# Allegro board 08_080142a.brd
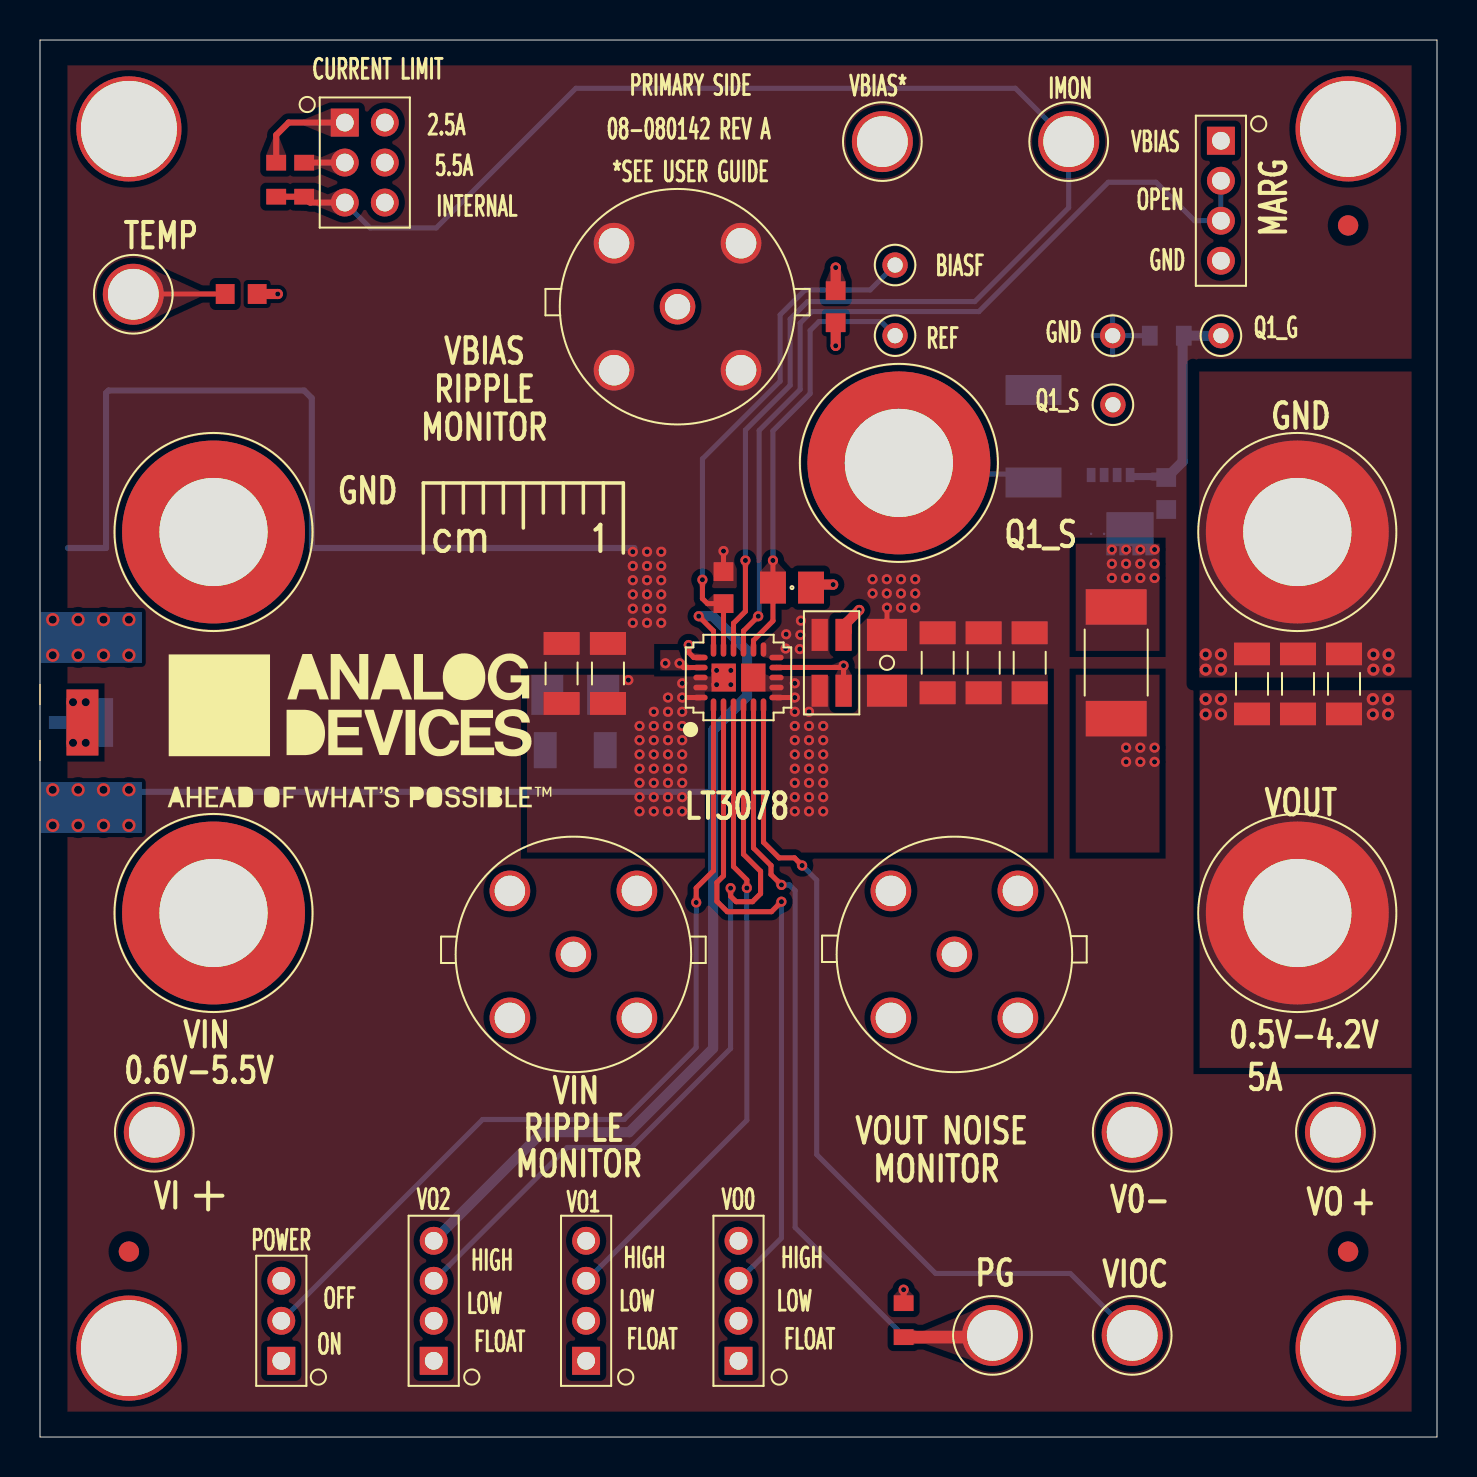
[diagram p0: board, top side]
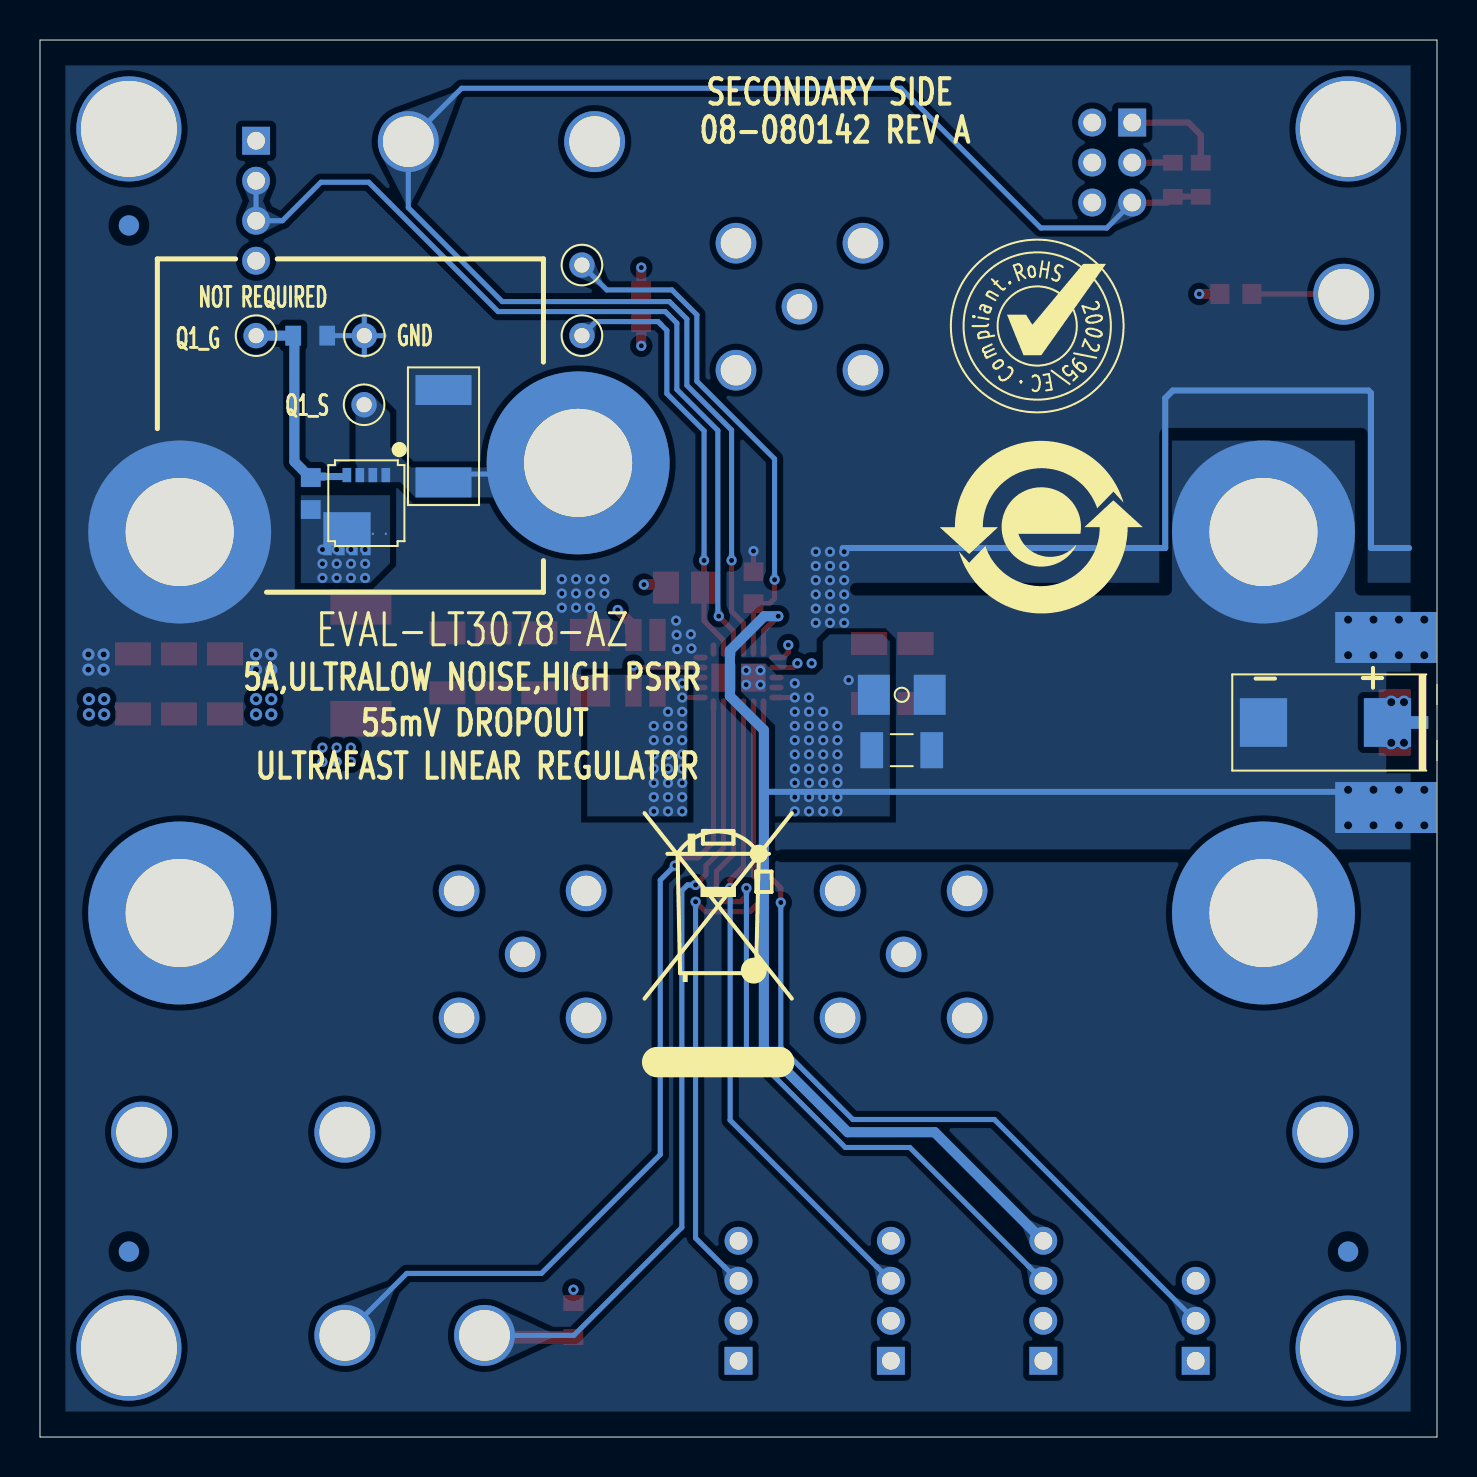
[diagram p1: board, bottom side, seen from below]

Outline 69.85 x 69.85 mm; copper layers: TOP, L2_GND, L3_VCC, BOTTOM. Coordinates in mm from the lower left corner of the outline.
Outline path: 0,69.85 0,0 69.85,0 69.85,69.85 0,69.85

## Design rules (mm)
constraint set DEFAULT: min track width 0.254
net group VBIAS: nets _N38 VBIAS
net group _N16: nets _N14 _N16 _N17
net group VOUT: nets _N86

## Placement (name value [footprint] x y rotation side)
C1  4.7UF  [C0805H60]  37.6 42.47 180 top
C2  2.2uF  [C0603]  34.17 42.47 270 top
C3  10UF  [C1206_SP]  39.58 38.71 270 top
C4  10UF  [C1206H71]  42.35 38.71 270 top
C5  220UF  [C7343-31]  5.58 35.73 0 bottom
C6  TBD0603  [C0603]  39.79 56.52 90 top
C7  TBD1206  [C1206]  44.88 38.71 270 top
C8  TBD1206  [C1206]  47.18 38.71 270 top
C9  TBD1206  [C1206]  49.48 38.71 270 top
C10  TBD1206  [C1206]  60.6 37.66 270 top
C11  TBD1206  [C1206]  62.9 37.66 270 top
C12  TBD1206  [C1206]  65.2 37.66 270 top
C13  TBD0603  [C0603]  10.06 57.15 180 top
C14  TBD1206  [C1206]  28.4 38.18 270 top
C15  TBD1206  [C1206]  26.08 38.18 90 top
C16  4700pF  [C0603]  56.31 47.17 270 bottom
CIN1  47UF  [C1206H71]  26.76 37.11 0 bottom
CIN2  TBD1206  [C1206]  26.76 34.34 180 bottom
E1  2501-2-00-80-00-00-07-0  [CNMILLMAX2501]  42.12 64.77 0 top
E2  2501-2-00-80-00-00-07-0  [CNMILLMAX2501]  4.66 57.14 0 top
E3  2501-2-00-80-00-00-07-0  [CNMILLMAX2501]  5.71 15.24 0 top
E4  2501-2-00-80-00-00-07-0  [CNMILLMAX2501]  47.62 5.08 0 top
E5  2501-2-00-80-00-00-07-0  [CNMILLMAX2501]  54.61 5.08 0 top
E6  2501-2-00-80-00-00-07-0  [CNMILLMAX2501]  54.61 15.24 0 top
E7  2501-2-00-80-00-00-07-0  [CNMILLMAX2501]  64.77 15.24 0 top
E8  2501-2-00-80-00-00-07-0  [CNMILLMAX2501]  51.44 64.77 0 top
J1  575-4  [CNBANANAD312LD203]  8.68 26.2 0 top
J2  575-4  [CNBANANAD312LD203]  8.68 45.25 0 top
J3  112404  [CNAMPHENOL112404]  26.67 24.13 0 top
J4  112404  [CNAMPHENOL112404]  31.88 56.52 0 top
J5  112404  [CNAMPHENOL112404]  45.72 24.13 0 top
J6  575-4  [CNBANANAD312LD203]  62.87 26.2 0 top
J7  575-4  [CNBANANAD312LD203]  62.87 45.25 0 top
J8  142-0701-851  [CNSMAL562W375H166]  0 35.73 180 bottom
J9  575-4  [CNBANANAD312LD203]  42.94 48.7 0 top
JP1  62000311121  [CNTHMHDR1X3L236W79H244]  12.07 3.81 90 top
JP2  62000411121  [CNTHMHDR1X4L315W79H250]  19.69 3.81 90 top
JP3  62000411121  [CNTHMHDR1X4L315W79H250]  27.3 3.81 90 top
JP4  62000411121  [CNTHMHDR1X4L315W79H250]  34.92 3.81 90 top
JP5  62000621121  [CNTHMHDR2X3L236W157H248]  15.24 65.72 270 top
JP6  62000411121  [CNTHMHDR1X4L315W79H250]  59.05 64.81 270 top
NOREF  -  []  0 0 0 top
NOREF#2  -  []  69.85 69.85 180 top
NOREF#3  -  []  154.94 85.09 0 top
NOREF#4  -  []  1.83 65.41 0 top
NOREF#5  -  []  0 69.85 0 top
NOREF#6  -  []  -60.22 175.56 0 top
NOREF#7  -  []  0 0 0 top
NOREF#8  -  [unnamed#2]  65.41 65.41 0 top
NOREF#9  -  []  16 35.31 0 top
NOREF#10  -  []  -111.76 -130.81 0 top
NOREF#11  -  []  0 0 0 top
NOREF#12  -  []  -60.33 196.51 0 top
NOREF#13  -  []  33.92 186.35 0 top
NOREF#14  -  []  306.27 180.04 90 top
NOREF#15  -  []  0 69.85 0 top
NOREF#16  -  []  37.72 62.99 270 top
NOREF#17  -  []  69.85 0 90 top
NOREF#18  -  []  -111.76 -130.81 0 top
NOREF#19  -  [unnamed#2]  4.45 9.27 0 top
NOREF#20  -  []  301.34 180.04 0 top
NOREF#21  -  []  67.77 36.22 0 top
NOREF#22  -  []  67.77 36.22 0 top
NOREF#23  -  []  233.88 183.85 180 top
NOREF#24  -  [unnamed#2]  4.45 65.41 0 top
NOREF#25  -  []  301.27 155.91 0 top
NOREF#26  -  []  0 0 0 top
NOREF#27  -  []  218.47 169.11 0 top
NOREF#28  -  []  218.64 181 0 top
NOREF#29  -  []  0 69.85 270 top
NOREF#30  -  [unnamed#2]  65.41 4.45 0 top
NOREF#31  -  [unnamed#2]  4.45 4.45 0 top
NOREF#32  -  []  66.12 191.41 0 top
NOREF#33  -  []  4.45 4.45 0 top
NOREF#34  -  []  67.77 36.22 0 top
NOREF#35  -  []  35.41 196.51 0 top
NOREF#36  -  []  -73.66 195.58 0 top
NOREF#37  -  []  69.85 0 0 top
NOREF#38  -  []  -111.76 -130.81 0 top
NOREF#39  -  []  0.43 35.73 0 top
NOREF#40  -  []  204.75 192.51 0 top
NOREF#41  -  []  69.85 0 90 top
NOREF#42  -  [unnamed#2]  65.41 60.58 0 top
NOREF#43  -  []  66.93 47.98 0 top
NOREF#44  -  []  178.82 174.9 0 top
NOREF#45  -  []  42.88 66.24 0 top
NOREF#46  -  [unnamed#2]  65.41 9.27 0 top
NOREF#47  -  []  0 0 0 top
NOREF#48  -  []  -60.18 202.21 0 top
NOREF#49  -  []  8.97 196.49 0 top
NOREF#50  -  []  4.45 4.45 0 top
NOREF#51  -  []  0 0 0 top
NOREF#52  -  []  283.59 348.62 0 top
NOREF#53  -  []  -111.76 -130.81 0 top
NOREF#54  -  [unnamed#2]  4.45 9.27 180 bottom
NOREF#55  -  []  19.99 55.55 180 bottom
NOREF#56  -  []  26.67 34.87 180 bottom
NOREF#57  -  [unnamed#2]  65.41 9.27 180 bottom
NOREF#58  -  [unnamed#2]  65.41 60.58 180 bottom
NOREF#59  -  []  19.79 45.49 180 bottom
Q1  FDMC8010  [POWER33]  53.53 46.69 0 bottom
R1  51K  [R0603]  43.18 5.84 90 top
R2  909  [R0603]  13.21 62.87 90 top
R3  2K  [R0603]  11.81 62.87 90 top
R4  TBD_SPACER_2512  [R2512]  53.81 38.71 270 top
R5  0.02  [R2010H35]  49.68 50.04 270 bottom
R6  10K  [R0603]  56.34 55.07 0 bottom
TP1  TESTPAD  [TPC50D30]  42.75 58.6 0 top
TP2  TESTPAD  [TPC50D30]  42.75 55.07 0 top
TP3  TESTPAD  [TPC50D30]  53.65 51.61 90 top
TP4  TESTPAD  [TPC50D30]  53.63 55.07 0 top
TP5  TESTPAD  [TPC50D30]  59.05 55.07 90 top
U1  LT3078AV#PBF  [QFN22_4X3-2PAD]  34.92 37.97 0 top

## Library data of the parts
C1 = CAP: Tolerance: 10; User Part Number: UPN; alternate symbols: (C0805H60); tolerance: 10
C2 C16 = CAP: User Part Number: UPN; Tolerance: 10; alternate symbols: (C0603); tolerance: 10
C3 = CAP_SP: User Part Number: UPN; Tolerance: 10; alternate symbols: (C1206_SP); tolerance: 10
C4 CIN1 = CAP: Tolerance: 10; User Part Number: UPN; alternate symbols: (C1206H71); tolerance: 10
C5 = CAPP: Tolerance: 20; User Part Number: UPN; alternate symbols: (C7343-31); tolerance: 20
C6 C13 = CAP: User Part Number: UPN; alternate symbols: (C0603)
C7-C12 C14 C15 CIN2 = CAP: User Part Number: UPN; alternate symbols: (C1206)
E1-E8 = CNTP1P: User Part Number: UPN; Tolerance: N/A; alternate symbols: (CNMILLMAX2501); tolerance: N/A
J1 J2 J6 J7 J9 = CNTP1P: Tolerance: N/A; User Part Number: UPN; alternate symbols: (CNBANANAD312LD203); tolerance: N/A
J3-J5 = CNBNC5P: Tolerance: N/A; User Part Number: UPN; alternate symbols: (CNAMPHENOL112404); tolerance: N/A
J8 = CNBNC5P: Tolerance: N/A; User Part Number: UPN; alternate symbols: (CNSMAL562W375H166); tolerance: N/A
JP1 = CN3P: User Part Number: UPN; Tolerance: N/A; alternate symbols: (CNTHMHDR1X3L236W79H244); tolerance: N/A
JP2-JP4 JP6 = CN4P: Tolerance: N/A; User Part Number: UPN; alternate symbols: (CNTHMHDR1X4L315W79H250); tolerance: N/A
JP5 = CN6P: User Part Number: UPN; Tolerance: N/A; alternate symbols: (CNTHMHDR2X3L236W157H248); tolerance: N/A
Q1 = TRANNMOSFET_V15: Tolerance: N/A; User Part Number: UPN; alternate symbols: (POWER33); tolerance: N/A
R1 R6 = RES: User Part Number: UPN; Tolerance: 5; alternate symbols: (R0603); tolerance: 5
R2 R3 = RES: User Part Number: UPN; Tolerance: 1; alternate symbols: (R0603); tolerance: 1
R4 = RES: Tolerance: N/A; User Part Number: UPN; alternate symbols: (R2512); tolerance: N/A
R5 = RES: Tolerance: 1; User Part Number: UPN; alternate symbols: (R2010H35); tolerance: 1
TP1-TP5 = NCTESTPAD: Tolerance: N/A; User Part Number: UPN; alternate symbols: (TPC50D30); tolerance: N/A
U1 = ADLT3078: User Part Number: UPN; Tolerance: N/A; alternate symbols: (QFN22_4X3-2PAD); tolerance: N/A

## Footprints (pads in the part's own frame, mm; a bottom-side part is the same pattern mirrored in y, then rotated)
C0603
  rect 0.94x0.991 smd: 1(-0.8,0) 2(0.8,0)
C0805H60
  rect 1.295x1.6 smd: 1(-0.953,0) 2(0.953,0)
C1206
  rect 1.143x1.803 smd: 1(-1.5,0) 2(1.5,0)
C1206_SP
  rect 1.6x0.813 smd: 1(-1.397,-0.597) 2(1.397,-0.597) 3(1.397,0.597) 4(-1.397,0.597)
C1206H71
  rect 1.6x2.007 smd: 1(-1.397,0) 2(1.397,0)
C7343-31
  rect 2.362x2.438 smd: N(3.1,0) P(-3.1,0)
CNAMPHENOL112404
  round 1.778 hole 1.27: 1(0,0)
  round 2.032 hole 1.524: 2(-3.175,3.175) 3(3.175,3.175) 4(3.175,-3.175) 5(-3.175,-3.175)
CNBANANAD312LD203
  round 9.144 hole 5.41: 1(0,0)
CNMILLMAX2501
  round 3.048 hole 2.54: 1(0,0)
CNSMAL562W375H166
  rect 1.727x0.635 smd: 1(-1.295,0)
  rect 5.08x2.54 smd: 2(-2.54,4.255) 3(-2.54,4.255) 4(-2.54,-4.255) 5(-2.54,-4.255)
CNTHMHDR1X3L236W79H244
  rect 1.397x1.397 hole 0.889: 1(0,0)
  round 1.397 hole 0.889: 2(2,0) 3(4,0)
CNTHMHDR1X4L315W79H250
  rect 1.397x1.397 hole 0.889: 1(0,0)
  round 1.397 hole 0.889: 2(2,0) 3(4,0) 4(6,0)
CNTHMHDR2X3L236W157H248
  rect 1.397x1.397 hole 0.889: 1(0,0)
  round 1.397 hole 0.889: 2(0,2) 3(2,0) 4(2,2) 5(4,0) 6(4,2)
POWER33
  rect 0.432x0.711 smd: 1(-0.975,-1.405) 2(-0.325,-1.405) 3(0.325,-1.405) 4(0.975,-1.405)
  custom 0.54x0.54 smd: 5(0.97,1.532)
  round 0.127 smd: 6(0.325,1.535) 7(-0.325,1.535) 8(-0.975,1.535)
QFN22_4X3-2PAD
  oval 0.279x0.711 smd: 1(-1.25,-1.4) 2(-0.75,-1.4) 3(-0.25,-1.4) 4(0.25,-1.4) 5(0.75,-1.4) 6(1.25,-1.4) 12(1.25,1.4) 13(0.75,1.4) 14(0.25,1.4) 15(-0.25,1.4) 16(-0.75,1.4) 17(-1.25,1.4)
  oval 0.711x0.279 smd: 7(1.9,-1) 8(1.9,-0.5) 9(1.9,0) 10(1.9,0.5) 11(1.9,1) 18(-1.9,1) 19(-1.9,0.5) 20(-1.9,0) 21(-1.9,-0.5) 22(-1.9,-1)
  rect 1.219x1.397 smd: PAD1(-0.74,0) PAD2(0.74,0)
R0603
  rect 0.787x0.991 smd: 1(-0.85,0) 2(0.85,0)
R2010H35
  rect 1.499x2.794 smd: 1(-2.311,0) 2(2.311,0)
R2512
  rect 1.778x3.048 smd: 1(-2.794,0) 2(2.794,0)
TPC50D30
  round 1.27 hole 0.762: 1(0,0)
unnamed#2
  round 5.258 hole 4.801 unplated: (0,0)

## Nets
GND1: J3.2 J3.3 J3.4 J3.5(SH4) U1.19
GND2: C1.1 C3.4(N4) E6.1(N1) J5.2 J5.3 J5.4 J5.5(SH4)
GND_POWER: C2.1 C3.1 C4.1 C5.N(N2) C6.1 C7.1 C8.1 C9.1 C10.1 C11.1 C12.1 C13.1 C14.1 C15.2(N2) CIN1.1 CIN2.2(N2) J2.1(N1) J4.2 J4.3 J4.4 J4.5(SH4) J7.1(N1) J8.2 J8.3 J8.4 J8.5(SH4) JP1.3(N3) JP2.2 JP3.2 JP4.2 JP5.2 JP5.4 JP5.6(N6) JP6.4(N4) R5.1 R6.1 TP4.1(N1) U1.11 U1.12
_N1: C5.P C14.2(N2) C15.1 CIN1.2(N2) CIN2.1 E3.1(N1) J1.1(N1) J3.1 J8.1 U1.20 U1.21 U1.22 U1.PAD1
_N14: E8.1(N1) JP5.5 R2.1 R3.1 U1.15
_N16: JP5.1 R3.2(N2)
_N17: JP5.3 R2.2(N2)
_N20: C1.2(N2) TP2.1(N1) U1.13
_N23: JP6.2 JP6.3 U1.14
_N30: C3.3 E7.1(N1) J5.1 U1.10
_N37: E5.1(N1) U1.6
_N38: E4.1(N1) R1.1 U1.5
_N40: JP1.2 U1.1
_N85: J9.1(N1) Q1.1 Q1.2 Q1.3(S3) R5.2(N2) TP3.1(N1)
_N86: C16.1 Q1.4 R6.2(N2) TP5.1(N1)
_N94: C13.2(N2) E2.1(N1) U1.18
_N97: C2.2(N2) TP1.1(N1) U1.16
_N108: C16.2(N2) Q1.5 Q1.6 Q1.7 Q1.8 R4.1
VBIAS: C6.2(N2) E1.1(N1) J4.1 JP1.1 JP2.4(N4) JP3.4(N4) JP4.4(N4) JP6.1 R1.2(N2) U1.17
VO0: JP4.3 U1.2
VO1: JP3.3 U1.3
VO2: JP2.3 U1.4(VO2)
VOUT: C3.2 C4.2(N2) C7.2(N2) C8.2(N2) C9.2(N2) C10.2(N2) C11.2(N2) C12.2(N2) J6.1(N1) R4.2(N2) U1.7 U1.8 U1.9 U1.PAD2

Pads without a net: JP2 1; JP3 1; JP4 1

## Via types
v1: diameter 0.508, hole 0.254, TOP to BOTTOM, 138 vias
v2: diameter 0.61, hole 0.305, TOP to BOTTOM, 16 vias
v3: diameter 0.66, hole 0.406, TOP to BOTTOM, 20 vias

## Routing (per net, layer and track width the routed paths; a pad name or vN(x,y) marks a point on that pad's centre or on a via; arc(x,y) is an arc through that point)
GND1: length 1.1
  TOP w0.254: v1(31.98,38.68) 32.19,38.47 U1.19
  vias: v1(31.27,38.68)
GND2: length 10.8
  TOP w0.508: v1(40.97,41.35) 40.34,40.72 40.34,40.26 C3.4 ; v1(39.66,42.62) 38.7,42.62 C1.1
  L2_GND w2.032: E6.1 J5.4
GND_POWER: length 18.4
  TOP w0.254: C2.1 v1(34.17,44.3) ; C4.1 v1(42.35,41.47)
  TOP w0.508: C13.1 v1(11.89,57.15) ; C6.1 v1(39.79,54.56)
  L2_GND w0.254: 58.25,59.61 JP6.4 ; JP6.4 59.84,59.61 ; JP6.4 58.25,58.02 ; JP6.4 59.84,58.02
  L3_VCC w0.254: 58.25,59.61 JP6.4 ; JP6.4 58.25,58.02 ; JP6.4 59.84,59.61 ; JP6.4 59.84,58.02
  BOTTOM w0.254: TP4.1 53.63,56.06 ; TP4.1 52.64,55.07 ; TP4.1 R6.1 ; TP4.1 53.63,54.08
  vias: v1(29.64,44.26) v1(29.64,43.55) v1(29.64,42.84) v1(29.64,42.13) v1(29.64,41.42) v1(29.64,40.71) v1(30.35,44.26) v1(30.35,43.55) v1(30.35,42.84) v1(30.35,42.13) v1(30.35,41.42) v1(30.35,40.71) v1(31.06,44.26) v1(31.06,43.55) v1(31.06,42.84) v1(31.06,42.13) v1(31.06,41.42) v1(31.06,40.71) v1(37.28,39.42) v1(37.31,40.14) v1(37.99,39.4) v1(38.05,40.82) v1(38.02,40.11) v1(41.63,42.89) v1(41.63,42.18) v1(42.34,42.89) v1(42.34,42.18) v1(43.05,42.89) v1(43.05,42.18) v1(43.05,41.47) v1(43.76,42.89) v1(43.76,42.18) v1(43.76,41.47) v2(58.29,39.13) v2(58.29,38.37) v2(59.05,39.13) v2(59.05,38.37) v2(66.67,39.13) v2(66.67,38.37) v2(67.43,39.13) v2(67.43,38.37) v3(0.64,40.87) v3(0.64,39.09) v3(0.64,32.36) v3(0.64,30.58) v3(1.91,40.87) v3(1.91,39.09) v3(1.91,32.36) v3(1.91,30.58) v3(3.18,40.87) v3(3.18,39.09) v3(3.18,32.36) v3(3.18,30.58) v3(4.45,40.87) v3(4.45,39.09) v3(4.45,32.36) v3(4.45,30.58)
_N1: length 40.4
  TOP w0.254: U1.22 v1(32.11,36.97)
  L2_GND w0.508: J3.1 26.67,30.02 28.09,31.44 28.09,36.52 v1(29.42,37.85)
  L3_VCC w0.508: E3.1 10.41,15.24 19.3,24.13 J3.1
  vias: v1(29.98,35.55) v1(29.98,34.84) v1(29.98,34.13) v1(29.98,33.42) v1(29.98,32.71) v1(29.98,31.99) v1(29.98,31.28) v1(30.69,36.26) v1(30.69,35.55) v1(30.69,34.84) v1(30.69,34.13) v1(30.69,33.42) v1(30.69,32.71) v1(30.69,31.99) v1(30.69,31.28) v1(31.4,36.97) v1(31.4,36.26) v1(31.4,35.55) v1(31.4,34.84) v1(31.4,34.13) v1(31.4,33.42) v1(31.4,32.71) v1(31.4,31.99) v1(31.4,31.28) v1(32.11,37.68) v1(32.11,36.26) v1(32.11,35.55) v1(32.11,34.84) v1(32.11,34.13) v1(32.11,33.42) v1(32.11,32.71) v1(32.11,31.99) v1(32.11,31.28) v1(33.83,38.33) v1(33.83,37.62) v1(34.54,38.33) v1(34.54,37.62) v3(1.65,36.74) v3(1.65,34.71) v3(2.29,36.74) v3(2.29,34.71)
_N14: length 81.5
  TOP w0.254: v1(35.27,43.83) 35.27,41.28 34.68,40.69 U1.15
  TOP w0.305: R3.1 R2.1 13.5,61.72 JP5.5
  BOTTOM w0.254: v1(35.27,43.83) 35.27,50.35 37.51,52.58 37.51,55.9 38.38,56.77 46.74,56.77 51.44,61.47 E8.1 48.77,67.44 26.8,67.44 19.81,60.45 16.51,60.45 JP5.5
_N16: length 5.1
  TOP w0.305: R3.2 11.81,65.1 12.43,65.72 JP5.1
_N17: length 2
  TOP w0.305: R2.2 13.34,63.72 JP5.3
_N20: length 21.8
  TOP w0.254: U1.13 35.68,39.83 36.65,40.8 C1.2 v1(36.65,43.83)
  BOTTOM w0.254: v1(36.65,43.83) 36.65,50.31 38.51,52.17 38.51,55.33 38.95,55.77 42.05,55.77 TP2.1
_N23: length 44.2
  TOP w0.254: v1(35.91,41.04) 35.17,40.3 U1.14
  BOTTOM w0.254: JP6.2 JP6.3 57.73,60.81 55.8,62.74 53.41,62.74 46.94,56.27 38.58,56.27 38.01,55.69 38.01,52.38 35.96,50.33 35.96,41.08 v1(35.91,41.04)
_N30: length 45
  TOP w0.254: C3.3 v1(40.18,38.57) 40.09,38.48 36.83,38.48 U1.10
  L2_GND w0.508: J5.1 45.72,34.54 41.69,38.57 v1(40.18,38.57)
  L3_VCC w0.508: E7.1 61.06,15.24 52.17,24.13 J5.1
_N37: length 43.5
  TOP w0.254: U1.6 36.17,29.74 36.96,28.96 37.73,28.96 v1(38.11,28.57)
  BOTTOM w0.254: E5.1 51.51,8.18 44.78,8.18 38.84,14.12 38.84,27.84 v1(38.11,28.57)
_N38: length 43.8
  TOP w0.254: U1.5 35.68,29.45 36.55,28.57 36.55,28.12 v1(37.07,27.6)
  TOP w0.635: E4.1 47.54,4.99 R1.1
  BOTTOM w0.254: v1(37.07,27.6) 37.47,27.6 37.76,27.32 37.76,10.48 43.15,5.08 E4.1
_N40: length 43.9
  TOP w0.254: U1.1 33.68,28.32 32.81,27.45 v1(32.81,26.73)
  BOTTOM w0.254: v1(32.81,26.73) 32.81,19.48 29.21,15.88 22.13,15.88 JP1.2
_N85: length 6.3
  BOTTOM w0.254: 48.85,47.75 48.46,48.15 43.5,48.15 J9.1
_N86: length 11.2
  BOTTOM w0.254: 55.88,48.02 55.93,47.97 C16.1
  BOTTOM w0.356: 55.62,48.02 54.58,48.02 Q1.4
  BOTTOM w0.406: 55.88,48.02 55.62,48.02
  BOTTOM w0.508: TP5.1 R6.2 57.13,55.01 57.13,48.77 56.34,47.97 C16.1
_N94: length 40.7
  TOP w0.254: E2.1 4.68,57.15 C13.2 ; U1.18 32.69,38.97 32.44,39.23 v1(32.44,39.6)
  L2_GND w0.254: v1(32.44,39.6) 32.01,40.02 29.09,40.02 13.82,55.3 6.51,55.3 E2.1
_N97: length 26
  TOP w0.254: v1(33.12,42.86) 33.12,41.92 33.37,41.67 C2.2 U1.16
  BOTTOM w0.254: TP1.1 41.51,57.35 38.25,57.35 37.01,56.11 37.01,52.79 33.12,48.9 v1(33.12,42.86)
_N108:
  vias: v1(53.59,44.37) v1(53.59,43.66) v1(53.59,42.95) v1(54.31,44.37) v1(54.31,43.66) v1(54.31,42.95) v1(55.02,44.37) v1(55.02,43.66) v1(55.02,42.95) v1(55.73,44.37) v1(55.73,43.66) v1(55.73,42.95)
VBIAS: length 195.2
  TOP w0.254: v1(32.94,41.04) 33.68,40.3 U1.17
  TOP w0.305: R1.2 v1(43.18,7.37)
  TOP w0.508: C6.2 v1(39.79,58.47)
  L2_GND w0.508: v1(32.94,41.04) 31.88,42.1 J4.1 37.83,56.52 v1(39.79,58.47) 39.79,62.44 E1.1
  L3_VCC w0.254: v1(43.18,7.37) 44.3,8.48 63.93,8.48 68.28,12.83 68.28,55.58 JP6.1
  L3_VCC w0.305: v1(43.18,7.37) 37.37,7.37 JP4.4 JP3.4 JP2.4 18.63,9.81 18.6,9.78 18.03,9.78 JP1.1
  BOTTOM w0.508: v1(32.94,41.04) 33.64,41.04 35.35,39.32 35.35,37.04 33.66,35.34 33.66,19.43 29.46,15.24 25.12,15.24 JP2.4
VO0: length 33.4
  TOP w0.254: v1(37.07,26.77) 36.57,26.27 34.36,26.27 33.84,26.79 33.84,27.73 34.17,28.06 U1.2
  BOTTOM w0.254: v1(37.07,26.77) 37.07,9.95 35.66,8.54 35.65,8.54 JP4.3
VO1: length 32.4
  TOP w0.254: v1(35.34,27.45) 35.34,27.85 34.68,28.52 U1.3
  BOTTOM w0.254: JP3.3 28.03,8.54 28.04,8.54 35.34,15.84 v1(35.34,27.45)
VO2: length 39.6
  TOP w0.254: v1(34.53,27.44) 34.53,27.04 34.8,26.76 35.63,26.76 36.03,27.17 36.03,28.28 35.17,29.14 U1.4
  BOTTOM w0.254: JP2.3 20.41,8.54 20.42,8.54 26.36,14.48 29.59,14.48 34.53,19.42 v1(34.53,27.44)
VOUT: length 0.9
  TOP w0.254: U1.7 v1(37.74,36.97)
  vias: v1(37.74,37.68) v1(37.74,36.26) v1(37.74,35.55) v1(37.74,34.84) v1(37.74,34.13) v1(37.74,33.42) v1(37.74,32.71) v1(37.74,31.99) v1(37.74,31.28) v1(38.45,36.26) v1(38.45,35.55) v1(38.45,34.84) v1(38.45,34.13) v1(38.45,33.42) v1(38.45,32.71) v1(38.45,31.99) v1(38.45,31.28) v1(39.16,35.55) v1(39.16,34.84) v1(39.16,34.13) v1(39.16,33.42) v1(39.16,32.71) v1(39.16,31.99) v1(39.16,31.28) v1(54.31,34.47) v1(54.31,33.76) v1(55.02,34.47) v1(55.02,33.76) v1(55.73,34.47) v1(55.73,33.76) v2(58.29,36.89) v2(58.29,36.13) v2(59.05,36.89) v2(59.05,36.13) v2(66.64,36.89) v2(66.64,36.13) v2(67.4,36.89) v2(67.4,36.13)

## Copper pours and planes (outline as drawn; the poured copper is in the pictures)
GND1 on TOP: 31.01,39.34 31.01,38.33 33.24,38.33 33.24,39.34
GND1 on L2_GND: 22.48,28.5 22.48,19.94 30.86,19.94 30.86,29.59 29.42,31.03 29.42,35.92 31.75,38.25 32.41,38.25 32.41,39.59 27.98,39.59 26.69,38.3 26.69,32.71
GND2 on L2_GND: 39.4,42.88 39.83,42.88 49.91,32.79 49.91,19.94 41.53,19.94 41.53,35.24 39.4,37.37
GND_POWER on TOP: 1.37,68.58 1.37,1.27 68.58,1.27 68.58,68.58
GND_POWER on BOTTOM: 1.32,68.58 68.58,68.58 68.58,1.27 1.32,1.27 ; 3 cut-outs
GND_POWER on L2_GND: 1.32,68.58 68.58,68.58 68.58,1.27 1.32,1.27 ; 1 cut-out
GND_POWER on L3_VCC: 1.37,68.58 68.58,68.58 68.58,1.27 1.37,1.27 ; 2 cut-outs
_N1 on TOP (solid shape): 2.92,34.07 1.32,34.07 1.32,37.38 2.92,37.38
_N1 on TOP: 33.24,29.22 33.24,37.27 34.79,37.27 34.79,38.11 24.35,38.11 24.35,29.22
_N1 on BOTTOM: 27.71,40.13 30.35,40.13 30.71,39.78 30.71,38.46 31.05,38.11 33.02,38.11 33.58,38.67 34.79,38.67 34.79,37.27 33.1,35.58 33.1,31.03 27.36,31.03 27.36,39.78
_N1 on L3_VCC: 34.79,37.36 34.79,38.58 32.97,38.58 32.97,37.36
_N1 on L3_VCC: 29.08,38.58 33.53,38.58 33.53,29.38 13.25,29.38 13.25,21.62 4.1,21.62 4.1,29.38 1.32,29.38 1.32,42.06 29.08,42.06 ; 1 cut-out
_N85 on BOTTOM: 42.12,48.48 51.3,48.48 52.34,49.52 52.34,51.2 53.21,52.08 53.23,52.08 54.12,51.19 54.07,51.14 54.07,47.74 51.84,47.74 51.07,46.98 42.12,46.98
_N108 on TOP: 55.97,39.31 51.78,39.31 51.78,44.66 55.97,44.66
_N108 on BOTTOM: 52.35,47.09 52.35,43.69 53.34,42.7 56.81,42.7 56.81,47.09
VOUT on TOP: 51.78,38.11 55.97,38.11 55.97,29.22 51.78,29.22
VOUT on TOP: 50.39,29.22 50.39,38.11 35.06,38.11 35.06,37.27 36.61,37.27 36.61,29.22
VOUT on TOP: 57.98,37.34 57.98,18.45 68.58,18.45 68.58,37.34
VOUT on BOTTOM: 37.49,31.03 37.49,38.11 42.49,38.11 42.49,31.03
VOUT on L3_VCC: 40.28,40.89 37.49,38.1 37.49,31.03 58.29,31.03 58.29,21.63 67.74,21.63 67.74,42.06 45.19,42.06 44.02,40.89

Small or netless copper shapes (teardrops, artwork), in the pictures only: 30 on TOP, 25 on BOTTOM, 7 on L2_GND, 14 on L3_VCC

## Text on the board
Ref Des/Silkscreen Bottom: GND | Q1_S | NOT REQUIRED | Q1_G | ULTRAFAST LINEAR REGULATOR | 55mV DROPOUT | 5A,ULTRALOW NOISE,HIGH PSRR | EVAL-LT3078-AZ
User.Comments: SEE NOTE 6 AT 4 PLACES | SEE DETAIL B | AT 8 PLACES | SEE DETAIL A | AT 5 PLACES | 5.    BOARDS TO BE SHIPPED SINGULATED AFTER ASSEMBLY PROCESS. | SMOOTHEN EDGES AND FREE FROM BURRS AFTER DEPANELIZATION PROCESS. | 7.    INSTALL SHUNT CONNECTOR MFG(60800213421) TO THE FOLLOWING HEADER CONNECTOR | JP1 PIN(1&2), JP2 PIN(1&2), JP3 PIN(1&2), JP4 PIN(3&4), JP5 PIN(3&4) & JP6 PIN(2&3)
Ref Des/Silkscreen Top: POWER | ON | OFF | CURRENT LIMIT | VO2 | 2.5A | 5.5A | INTERNAL | LOW | HIGH | FLOAT | VO1 | *SEE USER GUIDE | VO0 | VBIAS* | REF | BIASF | Q1_S | GND | IMON | VBIAS | OPEN | Q1_G | TEMP | VI | 0.6V-5.5V | VIN | RIPPLE | MONITOR | LT3078 | VOUT NOISE | PG | VIOC | V0- | 5A | VOUT | 0.5V-4.2V | VO | MARG
DIMENSION: FAB NOTES REVISION: 2ND NOVEMBER 2022 | 8.   IMPEDANCE REQUIREMENTS: IF NO STACKUP IS DEFINED, THE VENDOR IS ALLOWED TO ADJUST THE DIELECTRIC | 13.  PLATING SPECIFICATION: | 9.   FILLET OPTIONS TO ENHANCE RELIABILITY AT PAD JUNCTIONS WHERE SPACING PERMITS. | 10.  THIEVING: | 11.  LAYER TO LAYER REGISTRATION SHALL BE WITHIN 0.003 INCHES. | 12.  DRILL SIZES ARE FINISHED HOLE SIZES. ALL HOLES SHALL BE LOCATED WITHIN 0.005 INCHES DTP, | 14.  SURFACE FINISH: | 15.  SOLDERMASK: | 1.   DIMENSIONS ARE IN INCHES (EXCEPT WHERE NOTED). | ALL DOCUMENTS & SPECIFICATIONS REFERRED TO BELOW SHOULD BE THE LATEST REVISIONS. | 2.  BOARD MATERIAL:(USE CHECKED ITEMS) | 3.   ALL LAMINATES & BONDING MATERIALS SHOULD BE SELECTED FROM IPC-4101 OR IPC-4103,(TG>170 DEGC TD>300 DEGC) | 4.   REFER TO IPC-6010 SERIES, CLASS 2 FOR FABRICATION. | 5.   REFER TO LAMINATION DIAGRAM FOR OVERALL BOARD THICKNESS, TOLERANCE APPLIES AFTER ALL LAMINATION AND PLATING | 6.   BOW & TWIST NOT TO EXCEED 0.0075 INCHES (0.75%) PER LINEAR INCH AND SHOULD BE MEASURED PER IPC-TM-650, METHOD 2.4.22. | 7.   ACCEPTABILITY PER ADI SPECIFICATION TST00115. | 16.  APPLY SILKSCREEN TO BOTH SIDES USING A NON-CONDUCTIVE, EPOXY BASED INK PER ARTWORK. | ( ) FILLETS ALLOWED | (X) FILLETS NOT ALLOWED | ( ) VENDOR MAY ADD THIEVING TO COMPENSATE FOR LOW COPPER DENSITY AREAS MAINTAINING A MINIMUM | ( ) VENDOR MAY NOT ADD THIEVING TO COMPENSATE FOR LOW COPPER DENSITY AREAS. | (X) LPI | ( ) OTHER_________ | COLOR | (X) GREEN | (X) WHITE | ( ) OTHER | HINDER PROPER SOLDER WICKING. BARREL RELIEF ON SOLDERMASK ALLOWED IN UNFILLED VIA IN PAD HOLES. | (X) REFER TO LAMINATION DIAGRAM FOR FINISHED COPPER WEIGHT/THICKNESS REQUIRMENTS | (X) IMMERSION GOLD (ENIG) 1.58-3.94 MICRO INCHES OVER 118-236 MICRO INCHES MIN. OF ELECTROLESS NICKEL PER IPC-4552 | ( ) OSP (ORGANIC SOLDERABILITY PRESERVATIVE) | ( ) IMMERSION SILVER | ( ) SOFT WIRE BONDABLE GOLD 30-50 MICRO INCHES OF SOFT WIRE | ( ) EDGE CONNECTOR FINGERS ARE TO BE PLATED WITH 100 MICRO-INCHES(.0001") OF LOW STRESS | THICKNESS & TRACE WIDTHS TO MEET THE IMPEDANCE REQUIREMENT. IF SPECIFIED, THE VENDOR MUST | TRACE WIDTH & SPACING THAT IMPACT THE REQUIREMENTS MUST HAVE WRITTEN APPROVAL FROM ADI. | MINIMUM BARREL PLATING OF 0.001 INCHES. PLATED HOLES SHALL NOT BE ROUGH OR IRREGULAR SO AS TO | SOLDERMASK OVER BARE COPPER OR BARE GOLD (BOTH SIDES) TO MEET IPC-SM-840. | IF PRESENT,DO NOT MODIFY SOLDERMASK DEFINED PADS (MASK OPENINGS LESS THAN COPPER PAD) WITHOUT APPROVAL. | MEET THE REQUIREMENTS LISTED IN THE IMPEDANCE TABLE. ANY ADJUSTMENT MADE TO THE DEFINED STACKUP, | PROCESSES. FINISHED THICKNESS MEASURED FROM TOP COPPER TO BOTTOM COPPER. | (X) ISOLA 370HR OR S1000-2 OR IT180 OR EQUIVALENT | ( ) ISOLA FR408HR OR EQUIVALENT | ( ) ISOLA IS410 | ( ) MEGTRON 6 | ( ) NELCO 4000-13 | ( ) ROGERS 4350B | ( ) ROGERS 3003 | ( ) ARLON 85N | ( ) EM370D | ( ) OTHER ________________________ | UL FLAMMABILITY RATING 94V-0. BOARD MATERIAL & CONSTRUCTION SHALL MEET THE REQUIREMENTS OF UL796/UL796F. | BONDABLE GOLD OVER 100-150 MICRO INCHES OF NICKEL | NICKEL UNDER 30 MICRO-INCHES (.0003') OF GOLD | 0.100 INCH CLEARANCE FROM ALL COPPER FEATURES, | THE STARTING COPPER WEIGHT/THICKNESS CAN VARY AS LONG AS THE FINISHED COPPER | WEIGHT/THICKNESS IS NOT LESS THAN THE SPECIFIED VALUE. | UNLESS OTHERWISE SPECIFIED | HOMOGENOUS MATERIALS IN THIS BOARD SHALL BE COMPLAINT WITH THE EU DIRECTIVE 2002/95/EC | WORKMANSHIP SHALL CONFORM TO IPC-A-600, CLASS 2. | 21.  INTENTIONAL SHORTS: | 17.  FINAL ELECTRICAL TEST TO BE PERFORMED USING PROVIDED IPC-D-356A NETLIST OR ODB++ FORMAT FILE. | 22.  PEMNUTS: | 23.  MANUFACTURER TO ETCH/STAMP WITH PERMANENT NON-CONDUCTIVE INK | ON SECONDARY SIDE UNLESS OTHERWISE SPECIFIED: | 18.  A TIME DOMAIN REFLECTOMETER REPORT (TDR) FOR EACH IMPEDANCE CONTROLLED LAYER & A CERTIFICATE | 19.  IF PRESENT, ALL BLIND/BURIED VIAS WITH AN ASPECT RATIO <1:1 TO BE PLATED SHUT WITH COPPER WHEN | 20.  FOR VIA FILL INFORMATION REFER TO DRILL CHART: | 25. PANELIZATION: | 27.  MINIMUM DESIGN LINE WIDTH IS .010 INCH. | 28.  MINIMUM DESIGN LINE SPACING IS .008 INCH. | IS ACCEPTABLE, ALL OTHER INSTANCES MUST BE REPORTED. | IF AN INTENTIONAL SHORT REPORT IS SUPPLIED AND DOES NOT MATCH THE FAB DATA THEN | THE PCB SHALL HAVE A VERIFICATION STAMP. | ( )  NON-CONDUCTIVE EPOXY FILL ALL DRILLED VIAS | ( )  COPPER FILL ALL DRILLED VIAS | ( ) PEMNUTS TO BE INSTALLED BY FABRICATOR | ( ) PEMNUTS NOT TO BE INSTALLED BY FABRICATOR | ( ) NOT APPLICABLE | USED AS VIA-IN-PAD OR AS A STACKED VIA. BLIND/BURIED VIAS WITH AN ASPECT RATIO >1:1 TO BE FILLED | A. UL CODE-FLAMMABILITY RATING FOR THOSE APPROVED MATERIALS(IF APPLICABLE) | B. DATE CODE | C. LOT NUMBER | D. MANUFACTURER LOGO | BOARDS TO BE SHIPPED IN ARRAY AND KEPT INTACT | PANEL TO BE SUBJECTED TO CUSTOMERS APPROVAL | PANEL SOLDER PASTE STENCIL GERBER TO BE PROVIDED TO ANALOG | CAN'T BE PERFORMED BECAUSE THE TRACE LENGTH IS TOO SHORT ON THE OUTER LAYERS AT THE PIN ESCAPES | ADI APPROVAL IS REQUIRED. | OF COMPLIANCE SHALL BE PROVIDED BY VENDOR AT TIME OF SHIPMENT. INSTANCES WHERE TDR TESTING | WITH NON-CONDUCTIVE EPOXY. | TOOLING: | FINISH: | NOTES: | MATERIAL: | TESTING: | MISCELLANEOUS: | " " | (REF) | DIA MAX
PAGE_OUTLINE: BOARD Z
User.15: CORE | PREPEG
User.23: L2 GND | 08-      -07
User.24: L3 VCC | 08-      -08
User.45: FIGURE | SIZE | 10.0 | 12.0 | 16.0 | 30.0 | 35.0 | 50.0 | 60.0 | 100.0 | 213.0 | 189.0 | PLATED | NON-PLATED | DRILL CHART: TOP to BOTTOM | ALL UNITS ARE IN MILS | QTY | 138 | 16 | 20 | 5 | 25 | 3 | 12 | 8 | 4 | TOLERANCE/NOTES | A
